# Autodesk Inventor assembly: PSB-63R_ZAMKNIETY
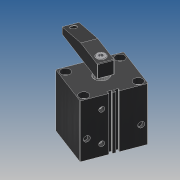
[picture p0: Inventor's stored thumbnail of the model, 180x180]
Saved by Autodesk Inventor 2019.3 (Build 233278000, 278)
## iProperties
Company: Î¢ÈíÖÐ¹ú
Created: 2013-04
Part Number: PSB-63R_ZAMKNIETY
Material: Ogólny
Description: STEP AP203
Document SubType Name: Assembly
Designer: CADENGINEERING4
Sending System: SolidWorks 2010
Preprocessor: SwSTEP 2.0
Title: PSB-L6390-1515-00.STEP
Author: Î¢ÈíÓÃ»§
Revision Number: ÈÎºÎ
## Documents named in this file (11)
- E:\SERWER_ZAPAS\Pneumatic\PSB PNEUMATIC SWING\PSB-63\PSB-63R_ZAMKNIETY.iam
- E:\SERWER_ZAPAS\Pneumatic\PSB PNEUMATIC SWING\PSB-63\PSB-L63-90-15-15-01.ipt
- E:\SERWER_ZAPAS\Pneumatic\PSB PNEUMATIC SWING\PSB-63\¸ÖÖé4.ipt
- E:\SERWER_ZAPAS\Pneumatic\PSB PNEUMATIC SWING\PSB-63\hex socket set screws with flat point gb_GB_FASTENER_SCREWS_HSFP M5X8-N.ipt
- E:\SERWER_ZAPAS\Pneumatic\PSB PNEUMATIC SWING\PSB-63\PSB-L63-90-15-15-04.ipt
- E:\SERWER_ZAPAS\Pneumatic\PSB PNEUMATIC SWING\PSB-63\PSB-L63-90-15-15-02.ipt
- E:\SERWER_ZAPAS\Pneumatic\PSB PNEUMATIC SWING\PSB-63\PSB-L63-90-15-15-05.ipt
- E:\SERWER_ZAPAS\Pneumatic\PSB PNEUMATIC SWING\PSB-63\hexagon socket head cap screws gb_GB_FASTENER_SCREWS_HSHCS M10X20-N.ipt
- E:\SERWER_ZAPAS\Pneumatic\PSB PNEUMATIC SWING\PSB-63\s¸Ë2.ipt
- E:\SERWER_ZAPAS\Pneumatic\PSB PNEUMATIC SWING\PSB-63\PSB-L63-90-15-15-03.ipt
- E:\SERWER_ZAPAS\Pneumatic\PSB PNEUMATIC SWING\PSB-63\4x40.ipt
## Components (14 placed, 14 different names)
1. PSB-L63-90-15-15-01_1 — Zestawiające:1, Zestawiające:2, Zestawiające:4, Kątowe:1
2. ¸ÖÖé4_2 — Zestawiające:10
3. hex socket set screws with flat point gb_GB_FASTENER_SCREWS_HSFP M5X8-N_3 — Zestawiające:10
4. hex socket set screws with flat point gb_GB_FASTENER_SCREWS_HSFP M5X8-N_4 — Zestawiające:12
5. PSB-L63-90-15-15-04_5 — Zestawiające:5, Równoległe:1, Zestawiające:6, Zestawiające:9, Kątowe:1
6. PSB-L63-90-15-15-02_6 — Zestawiające:3, Zestawiające:4, Zestawiające:5, Zestawiające:13, Równoległe:2
7. PSB-L63-90-15-15-05_7 — Równoległe:1, Zestawiające:6, Zestawiające:8, Zestawiające:14
8. ¸ÖÖé4_8 — Zestawiające:12
9. hexagon socket head cap screws gb_GB_FASTENER_SCREWS_HSHCS M10X20-N_9 — Zestawiające:1, Zestawiające:2, Zestawiające:3
10. s¸Ë2_10 — Zestawiające:7, Zestawiające:9
11. ¸ÖÖé4_11 — Zestawiające:11
12. PSB-L63-90-15-15-03_12 — Zestawiające:13, Równoległe:2, Zestawiające:14
13. 4x40_13 — Zestawiające:7, Zestawiające:8
14. hex socket set screws with flat point gb_GB_FASTENER_SCREWS_HSFP M5X8-N_14 — Zestawiające:11
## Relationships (17: Mate 14, Flush 2, Angle 1)
- Zestawiające:1 [Mate]: PSB-L63-90-15-15-01_1 ↔ hexagon socket head cap screws gb_GB_FASTENER_SCREWS_HSHCS M10X20-N_9
- Zestawiające:2 [Mate]: PSB-L63-90-15-15-01_1 ↔ hexagon socket head cap screws gb_GB_FASTENER_SCREWS_HSHCS M10X20-N_9
- Zestawiające:3 [Mate]: PSB-L63-90-15-15-02_6 ↔ hexagon socket head cap screws gb_GB_FASTENER_SCREWS_HSHCS M10X20-N_9
- Zestawiające:4 [Mate]: PSB-L63-90-15-15-01_1 ↔ PSB-L63-90-15-15-02_6
- Zestawiające:5 [Mate]: PSB-L63-90-15-15-04_5 ↔ PSB-L63-90-15-15-02_6
- Równoległe:1 [Flush]: PSB-L63-90-15-15-04_5 ↔ PSB-L63-90-15-15-05_7
- Zestawiające:6 [Mate]: PSB-L63-90-15-15-04_5 ↔ PSB-L63-90-15-15-05_7
- Zestawiające:7 [Mate]: s¸Ë2_10 ↔ 4x40_13
- Zestawiające:8 [Mate]: PSB-L63-90-15-15-05_7 ↔ 4x40_13
- Zestawiające:9 [Mate]: PSB-L63-90-15-15-04_5 ↔ s¸Ë2_10
- Zestawiające:10 [Mate]: ¸ÖÖé4_2 ↔ hex socket set screws with flat point gb_GB_FASTENER_SCREWS_HSFP M5X8-N_3
- Zestawiające:11 [Mate]: ¸ÖÖé4_11 ↔ hex socket set screws with flat point gb_GB_FASTENER_SCREWS_HSFP M5X8-N_14
- Zestawiające:12 [Mate]: hex socket set screws with flat point gb_GB_FASTENER_SCREWS_HSFP M5X8-N_4 ↔ ¸ÖÖé4_8
- Zestawiające:13 [Mate]: PSB-L63-90-15-15-02_6 ↔ PSB-L63-90-15-15-03_12
- Równoległe:2 [Flush]: PSB-L63-90-15-15-02_6 ↔ PSB-L63-90-15-15-03_12
- Kątowe:1 [Angle]: PSB-L63-90-15-15-01_1 ↔ PSB-L63-90-15-15-04_5
- Zestawiające:14 [Mate]: PSB-L63-90-15-15-05_7 ↔ PSB-L63-90-15-15-03_12
